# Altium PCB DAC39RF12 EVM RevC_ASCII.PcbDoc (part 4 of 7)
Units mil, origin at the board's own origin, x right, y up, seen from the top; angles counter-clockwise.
Board outline 5071.81 x 2716.54 mil, 16 copper layers (Top Layer, L2 GND1, L3 PWR1, L4 GND2, L5 PWR2, L6 GND3, L7 Ctrl Signal 1, L8 GND4, L9 GND5, L10 Ctrl Signal 2, L11 GND6, L12 PWR3, L13 GND7, L14 PWR4, L15 GND8, Bottom Layer), stack 82.4 mil thick; 596 components, 375 nets, 3310 pads, 1662 vias.
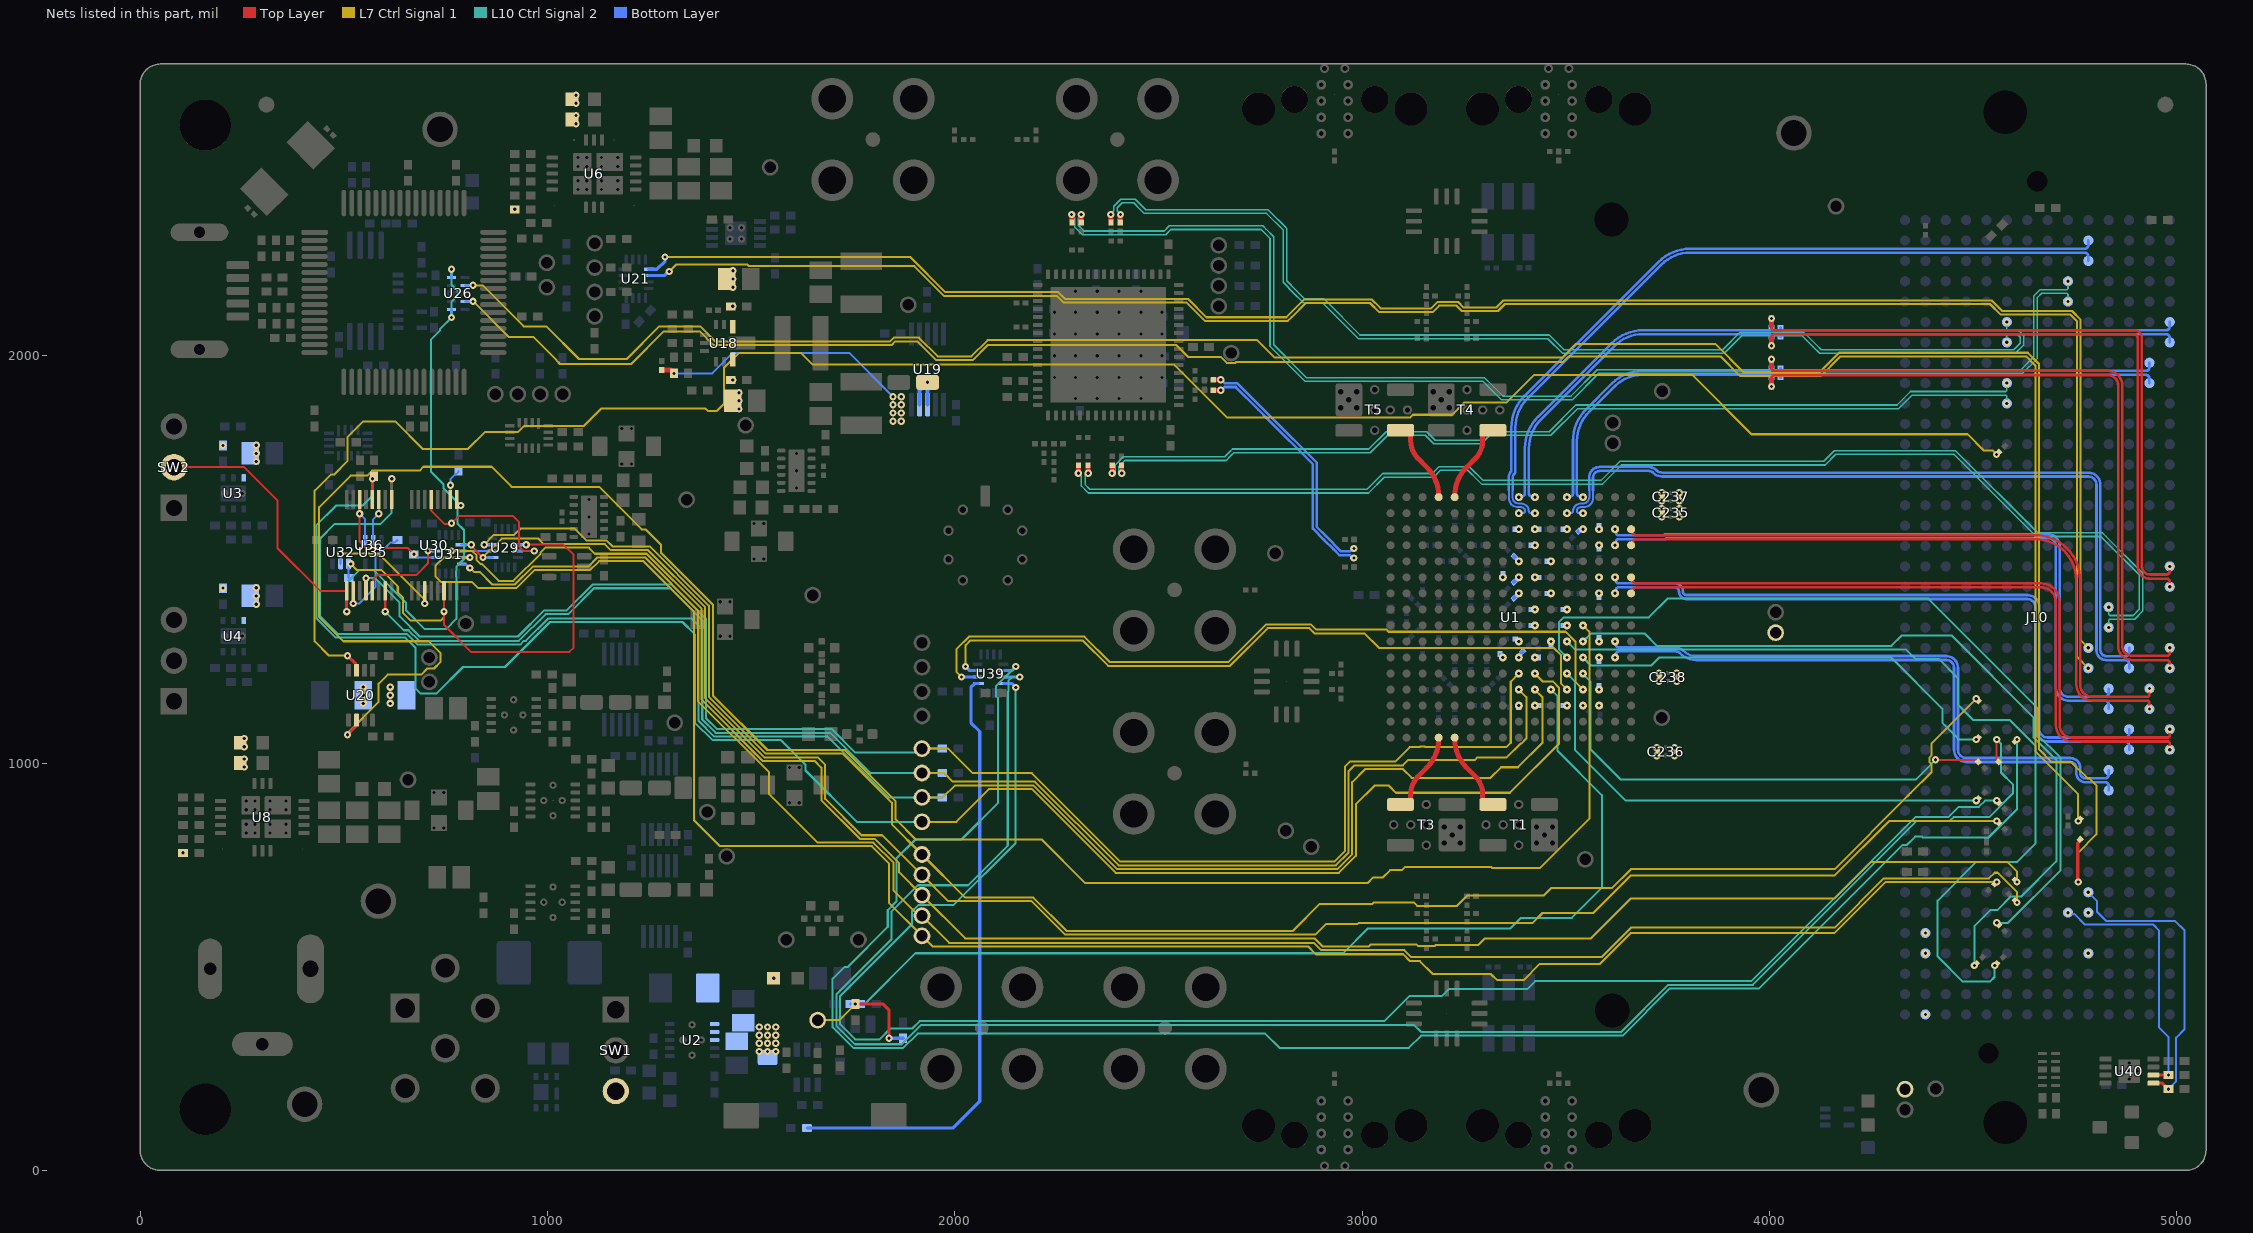
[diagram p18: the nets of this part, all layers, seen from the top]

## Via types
v1: diameter 18, hole 8, Top Layer to Bottom Layer, tented both sides, 1558 vias
v2: diameter 20, hole 10, Top Layer to Bottom Layer, tented both sides, 92 vias
v3: diameter 27, hole 15, Top Layer to Bottom Layer, tented both sides, 12 vias

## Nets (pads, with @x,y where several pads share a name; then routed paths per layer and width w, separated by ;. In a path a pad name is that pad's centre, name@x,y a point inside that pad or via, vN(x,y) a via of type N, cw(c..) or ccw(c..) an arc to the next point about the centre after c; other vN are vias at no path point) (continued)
7SRX_n: J10.B28 U1.G2 | length 1506.9
  Bottom Layer w6.25: v1(3620.99,1298.73) cw(c3615.56,1293.31) 3623.24,1293.31 3623.24,1290.32 ccw(c3629.64,1290.32) 3625.11,1285.8 ccw(c3629.64,1290.33) 3629.64,1283.92 3769.94,1283.92 cw(c3769.94,1258.81) 3787.7,1276.57 ccw(c3820.36,1309.23) 3820.36,1263.04 4433.61,1263.04 cw(c4433.61,1233.82) 4462.84,1233.82 4462.84,1228.44 ; 4462.8,1228.44 4462.8,1033.06 ccw(c4483.23,1033.06) 4483.23,1012.63 4738.89,1012.63 cw(c4738.89,988.86) 4762.66,988.86 4762.66,976.61 ccw(c4776.34,976.61) 4776.34,962.93 4823.97,962.93 ccw(c4823.97,971.77) 4832.81,971.77 J10.B28@4832.81,983.06
7SRX_p: J10.B29 U1.F2 | length 1506.9
  Bottom Layer w6.25: v1(3620.99,1259.36) ccw(c3615.56,1264.79) 3623.24,1264.79 3623.24,1267.77 cw(c3629.64,1267.77) 3625.11,1272.3 cw(c3629.64,1267.77) 3629.64,1274.17 3769.94,1274.17 cw(c3769.94,1258.81) 3780.8,1269.67 ccw(c3820.36,1309.23) 3820.36,1253.29 4433.61,1253.29 cw(c4433.61,1233.82) 4453.09,1233.82 4453.09,1228.44 ; 4453.05,1228.44 4453.05,1033.06 ccw(c4483.23,1033.06) 4483.23,1002.88 4738.89,1002.88 cw(c4738.89,988.86) 4752.91,988.86 4752.91,976.61 ccw(c4776.34,976.61) 4776.34,953.18 4823.97,953.18 cw(c4823.97,944.34) 4832.81,944.34 J10.B29@4832.81,933.06
8SRX_n: R97.2 R98.2 U1.T8 | length 887
  Bottom Layer w6.25: v1(3384.77,1653.06) cw(c3390.19,1647.64) 3390.19,1655.31 3393.18,1655.31 ccw(c3393.18,1661.71) 3397.7,1657.19 ccw(c3393.17,1661.71) 3399.58,1661.71 3399.58,1772.67 cw(c3509.33,1772.67) 3431.72,1850.27 3612.23,2030.79 cw(c3689.84,1953.18) 3689.84,2062.93 3998.37,2062.93 ; 3998.37,2062.93 ccw(c3998.37,2069.56) R97.2@4005,2069.56 cw(c3998.37,2069.56) 3998.37,2062.93
8SRX_p: R99.2 R100.2 U1.T7 | length 871.7
  Bottom Layer w6.25: v1(3424.14,1653.06) ccw(c3418.71,1647.64) 3418.71,1655.31 3415.73,1655.31 cw(c3415.73,1661.71) 3411.2,1657.19 cw(c3415.73,1661.71) 3409.33,1661.71 3409.33,1772.67 cw(c3509.33,1772.67) 3438.62,1843.38 3619.13,2023.89 cw(c3689.84,1953.18) 3689.84,2053.18 3998.37,2053.18 ; 3998.37,2053.18 cw(c3998.37,2046.56) R99.2@4005,2046.56 ccw(c3998.37,2046.56) 3998.37,2053.18
9SRX_n: J10.C2 U1.R8 | length 1882.7
  Bottom Layer w5: 3359.84,1670.39 3360.22,1670.02 3360.22,1650.32 ccw(c3382,1650.32) 3382,1628.54 3388.94,1628.54 cw(c3388.94,1616.08) 3397.74,1624.89 cw(c3392.4,1619.55) 3399.95,1619.55 cw(c3394.09,1619.55) 3394.09,1613.69 v1(3384.77,1613.69)
  Bottom Layer w6.25: 3359.84,1670.39 3359.84,1701.31 cw(c3380.81,1701.31) 3365.98,1716.13 ccw(c3364.75,1717.37) 3366.49,1717.37 3366.49,1824.01 cw(c3476.24,1824.01) 3398.64,1901.62 ; 3398.64,1901.62 3727.81,2230.79 cw(c3805.41,2153.18) 3805.41,2262.93 4773.97,2262.93 ccw(c4773.97,2271.77) 4782.81,2271.77 J10.C2@4782.81,2283.06
9SRX_p: J10.C3 U1.R7 | length 1866.1
  Bottom Layer w5: 3369.59,1670.43 3369.22,1670.06 3369.22,1653.16 ccw(c3384.85,1653.16) 3384.85,1637.54 3389.02,1637.54 cw(c3389.02,1616.29) 3404.04,1631.31 3404.15,1631.21 cw(c3392.54,1619.61) 3408.95,1619.61 3408.95,1619.55 ccw(c3414.81,1619.55) 3414.81,1613.69 v1(3424.14,1613.69)
  Bottom Layer w6.25: 3369.59,1670.43 3369.59,1701.31 cw(c3380.81,1701.31) 3372.88,1709.24 ccw(c3364.75,1717.37) 3376.24,1717.37 3376.24,1824.01 cw(c3476.24,1824.01) 3405.53,1894.72 3734.7,2223.89 cw(c3805.41,2153.18) 3805.41,2253.18 4773.97,2253.18 cw(c4773.97,2244.34) 4782.81,2244.34 J10.C3@4782.81,2233.06
10SRX_n: R92.2 R93.2 U1.T5 | length 728.1
  Bottom Layer w6.25: v1(3502.88,1653.06) cw(c3508.31,1647.64) 3508.31,1655.31 3511.29,1655.31 ccw(c3511.29,1661.71) 3515.81,1657.19 ccw(c3511.29,1661.71) 3517.69,1661.71 3517.69,1790.89 cw(c3627.44,1790.89) 3549.83,1868.49 3614.09,1932.75 cw(c3686.95,1859.9) 3686.95,1962.93 3998.38,1962.93 ccw(c3998.38,1969.56) R92.2@4005,1969.56
10SRX_p: R94.2 R96.2 U1.T4 | length 712.8
  Bottom Layer w6.25: v1(3542.25,1653.06) ccw(c3536.82,1647.64) 3536.82,1655.31 3533.84,1655.31 cw(c3533.84,1661.71) 3529.31,1657.19 cw(c3533.84,1661.71) 3527.44,1661.71 3527.44,1790.89 cw(c3627.44,1790.89) 3556.73,1861.6 3620.99,1925.86 cw(c3686.95,1859.9) 3686.95,1953.18 3998.38,1953.18 cw(c3998.38,1946.56) R94.2@4005,1946.56
11SRX_n: J10.A22 U1.R5 | length 1917.1
  Bottom Layer w5: v1(3502.88,1613.69) 3512.2,1613.69 ccw(c3512.2,1619.55) 3518.06,1619.55 3518.06,1619.61 cw(c3534.47,1619.61) 3522.87,1631.21 3522.97,1631.31 cw(c3537.99,1616.29) 3537.99,1637.54 3542.17,1637.54 ccw(c3542.17,1653.16) 3557.8,1653.16 3557.8,1670.06
  Bottom Layer w6.25: 3557.05,1669.98 3557.05,1700.89 cw(c3583.27,1700.89) 3583.27,1727.12 3703.64,1727.12 cw(c3703.64,1701.74) 3721.59,1719.68 ccw(c3736.7,1734.79) 3736.7,1713.42 4782.21,1713.42 cw(c4782.21,1683.06) 4812.58,1683.06 4812.58,1276.69 ccw(c4826.34,1276.69) 4826.34,1262.93 4873.97,1262.93 ccw(c4873.97,1271.77) 4882.81,1271.77 J10.A22@4882.81,1283.06
11SRX_p: J10.A23 U1.R4 | length 1902.9
  Bottom Layer w5: v1(3542.25,1613.69) 3532.92,1613.69 cw(c3532.92,1619.55) 3527.06,1619.55 cw(c3534.61,1619.55) 3529.27,1624.89 cw(c3538.08,1616.08) 3538.08,1628.54 3545.01,1628.54 ccw(c3545.01,1650.32) 3566.8,1650.32 3566.8,1670.02
  Bottom Layer w6.25: 3566.8,1670.02 3566.8,1700.89 cw(c3583.27,1700.89) 3583.27,1717.37 3703.64,1717.37 cw(c3703.64,1701.74) 3714.69,1712.79 ccw(c3736.7,1734.79) 3736.7,1703.67 4782.21,1703.67 cw(c4782.21,1683.06) 4802.83,1683.06 4802.83,1276.69 ccw(c4826.34,1276.69) 4826.34,1253.18 4873.97,1253.18 cw(c4873.97,1244.34) 4882.81,1244.34 J10.A23@4882.81,1233.06
12SRX_n: J10.Z24 U1.P1 | length 1635.6
  Top Layer w6.25: U1.P1@3660.36,1574.32 ccw(c3675.17,1574.32) 3675.17,1559.51 3698.74,1559.51 4653.05,1559.51 cw(c4653.05,1449.76) 4762.8,1449.76 4762.8,1192.51 ccw(c4792.39,1192.51) 4792.39,1162.93 4927.73,1162.93 ccw(c4927.73,1168.01) 4932.81,1168.01 v1(4932.81,1183.06)
12SRX_p: J10.Z25 U1.N1 | length 1634.9
  Top Layer w6.25: U1.N1@3660.36,1534.95 cw(c3675.17,1534.95) 3675.17,1549.76 4653.05,1549.76 cw(c4653.05,1449.76) 4753.05,1449.76 4753.05,1216.05 ccw(c4815.92,1216.05) 4753.51,1208.47 cw(c4747.3,1207.75) 4753.55,1207.79 4753.55,1192.51 ccw(c4792.39,1192.51) 4792.39,1153.68 4807.66,1153.68 cw(c4807.62,1147.43) 4808.34,1153.64 ccw(c4815.92,1216.05) 4815.92,1153.18 4927.73,1153.18 cw(c4927.73,1148.1) 4932.81,1148.1 v1(4932.81,1133.06)
12V: "U6. "@1065.09,2530 "U8. "@250.73,950.35 C8.2 C9.2 C12.2 C14.2 C19.2 C29.2 C30.2 C33.2 C86.2 C87.2 C88.2 C89.2 D1.1 D3.1 F1.1 R26.2 R28.2 R30.2 R36.2 R47.2 U2.6 U2.7 U2.8 U3.6 U4.6 U18.8 U18.12 | length 113.1
  Top Layer w8: v1(255.73,990.35) C30.2@245.73,1000.35 v1(255.73,1010.35) ; v1(255.73,1040.35) C33.2@245.73,1050.35 v1(255.73,1060.35) ; v1(1070.09,2570) C19.2@1060.09,2580 v1(1070.09,2590) ; v1(1070.09,2620) C29.2@1060.09,2630 v1(1070.09,2640)
  other v1: 1520.24,292.22 1540.24,292.22 1560.24,292.22 1520.24,312.22 1540.24,312.22 1560.24,312.22 1520.24,332.22 1540.24,332.22 1560.24,332.22 1520.24,352.22 1540.24,352.22 1560.24,352.22 1555.26,471.85 105.4,779.98 614.03,1146.72 614.03,1166.72 614.03,1186.72 285.31,1390.42 285.31,1410.42 203.38,1429.79 285.31,1430.42 285.31,1740.42 285.31,1760.42 203.38,1779.79 285.31,1780.42 1470.1,1869.53 1470.1,1889.53 1470.1,1909.53 1455.09,1940.83 1455.09,2121.53 1455.25,2168.58 1455.25,2188.58 1455.25,2208.58 919.76,2359.63
12V_FMC: J10.C35 J10.C37 J10.L36 J10.L37 J10.L40 PP48.1 SW1.3
  other v1: 4382.81,383.06 4382.81,533.06 4782.81,533.06 4382.81,583.06 4782.81,633.06
13SRX_n: J10.B24 U1.P2 | length 1617.3
  Bottom Layer w6.25: v1(3620.99,1574.32) cw(c3615.56,1568.9) 3623.24,1568.9 3623.24,1565.92 ccw(c3629.64,1565.92) 3625.11,1561.39 ccw(c3629.64,1565.92) 3629.64,1559.51 3740.59,1559.51 3743.5,1562.42 4083.63,1562.42 4344.98,1562.43 4663.32,1562.42 cw(c4663.32,1552.68) 4665.77,1562.11 ccw(c4667.29,1568.17) 4667.25,1561.92 4678.9,1561.92 ccw(c4678.87,1568.17) 4680.37,1562.1 cw(c4682.79,1552.68) 4682.79,1562.41 cw(c4682.81,1532.78) 4712.44,1532.78 4712.44,1184.67 ccw(c4734.18,1184.67) 4734.18,1162.93 4823.97,1162.93 ccw(c4823.97,1171.77) 4832.81,1171.77 J10.B24@4832.81,1183.06
13SRX_p: J10.B25 U1.N2 | length 1617
  Bottom Layer w6.25: v1(3620.99,1534.95) ccw(c3615.56,1540.38) 3623.24,1540.38 3623.24,1543.36 cw(c3629.64,1543.36) 3625.11,1547.89 cw(c3629.64,1543.36) 3629.64,1549.76 3744.63,1549.76 3747.54,1552.67 4087.67,1552.67 ; 4087.68,1552.68 4340.94,1552.68 4382.04,1552.67 ccw(c4382.01,1558.92) 4382.19,1552.67 cw(c4382.81,1533.06) 4383.41,1552.67 ccw(c4383.61,1558.92) 4383.57,1552.67 4432.04,1552.67 ccw(c4432.01,1558.92) 4432.19,1552.67 cw(c4432.81,1533.06) 4433.41,1552.67 ccw(c4433.61,1558.92) 4433.57,1552.67 4482.04,1552.67 ccw(c4482.01,1558.92) 4482.19,1552.67 cw(c4482.81,1533.06) 4483.41,1552.67 ccw(c4483.61,1558.92) 4483.57,1552.67 4532.04,1552.67 ccw(c4532.01,1558.92) 4532.19,1552.67 cw(c4532.81,1533.06) 4533.41,1552.67 ccw(c4533.61,1558.92) 4533.57,1552.67 4582.04,1552.67 ccw(c4582.01,1558.92) 4582.19,1552.67 cw(c4582.81,1533.06) 4583.41,1552.67 ccw(c4583.61,1558.92) 4583.57,1552.67 4632.04,1552.67 ccw(c4632.01,1558.92) 4632.19,1552.67 cw(c4632.81,1533.06) 4633.41,1552.67 ccw(c4633.61,1558.92) 4633.57,1552.67 4682.04,1552.67 ccw(c4682.01,1558.92) 4682.19,1552.67 cw(c4682.81,1533.06) 4682.81,1552.68 cw(c4682.81,1533.06) 4683.71,1552.66 ccw(c4683.96,1558.9) 4683.89,1552.66 cw(c4683.8,1533.77) 4702.69,1533.77 4702.69,1187.06 ccw(c4736.56,1187.06) 4703.86,1178.23 cw(c4697.81,1176.63) 4703.91,1178.01 ccw(c4734.18,1184.67) 4727.47,1154.41 cw(c4726.14,1148.31) 4727.74,1154.35 ccw(c4736.56,1187.06) 4736.56,1153.18 4823.97,1153.18 cw(c4823.97,1144.34) 4832.81,1144.34 J10.B25@4832.81,1133.06
14SRX_n: J10.Y26 U1.L1 | length 1694.7
  Top Layer w6.25: U1.L1@3660.36,1456.21 ccw(c3675.17,1456.21) 3675.17,1441.4 3698.74,1441.4 4666.63,1441.4 cw(c4666.63,1395.6) 4712.44,1395.6 4712.44,1093.14 ccw(c4742.64,1093.14) 4742.64,1062.93 4977.73,1062.93 ccw(c4977.73,1068.01) 4982.81,1068.01 v1(4982.81,1083.06)
14SRX_p: J10.Y27 U1.K1 | length 1694
  Top Layer w6.25: U1.K1@3660.36,1416.84 cw(c3675.17,1416.84) 3675.17,1431.65 4666.63,1431.65 cw(c4666.63,1395.6) 4702.69,1395.6 4702.69,1116.68 ccw(c4766.18,1116.68) 4703.14,1109.05 cw(c4696.94,1108.34) 4703.19,1108.37 4703.19,1093.14 ccw(c4742.64,1093.14) 4742.64,1053.68 4757.88,1053.68 cw(c4757.85,1047.43) 4758.56,1053.64 ccw(c4766.18,1116.68) 4766.18,1053.18 4977.73,1053.18 cw(c4977.73,1048.1) 4982.81,1048.1 v1(4982.81,1033.06)
15SRX_n: J10.A26 U1.L2 | length 1633.4
  Bottom Layer w6.25: v1(3620.99,1456.21) cw(c3615.56,1450.79) 3623.24,1450.79 3623.24,1447.81 ccw(c3629.64,1447.81) 3625.11,1443.28 ccw(c3629.64,1447.81) 3629.64,1441.4 3767.54,1441.4 cw(c3767.54,1421.3) 3787.64,1421.3 ccw(c3796.15,1421.3) 3796.15,1412.79 4632.81,1412.79 cw(c4632.81,1383.07) 4662.53,1383.07 4662.53,1083.06 ccw(c4682.65,1083.06) 4682.65,1062.93 4873.97,1062.93 ccw(c4873.97,1071.77) 4882.81,1071.77 J10.A26@4882.81,1083.06
15SRX_p: J10.A27 U1.K2 | length 1633.4
  Bottom Layer w6.25: v1(3620.99,1416.84) ccw(c3615.56,1422.27) 3623.24,1422.27 3623.24,1425.25 cw(c3629.64,1425.25) 3625.11,1429.78 cw(c3629.64,1425.25) 3629.64,1431.65 3767.54,1431.65 cw(c3767.54,1421.3) 3777.89,1421.3 ccw(c3796.15,1421.3) 3796.15,1403.04 4632.81,1403.04 cw(c4632.81,1383.07) 4652.78,1383.07 4652.78,1083.06 ccw(c4682.65,1083.06) 4682.65,1053.18 4873.97,1053.18 cw(c4873.97,1044.34) 4882.81,1044.34 J10.A27@4882.81,1033.06
CCLK_SHIFT: J10.C22 U21.9 | length 4474.9
  L7 Ctrl Signal 1 w5: v1(1288.71,2242.7) 1890.69,2242.7 1976.84,2156.55 2254.21,2156.55 2271.21,2139.55 2572.7,2139.55 2617.58,2094.68 2814.13,2094.68 2858.16,2138.71 3023.06,2138.71 3045.47,2116.3 3169.31,2116.3 3185.36,2132.35 3235.33,2132.35 3248.65,2119.03 3329.78,2119.03 3347.04,2136.29 4545.04,2136.29 4571.33,2110 4742.73,2110 4764,2088.73 4764,1301.87 v1(4782.81,1283.06)
  Bottom Layer w8: U21.9@1248.71,2212.7 1268.71,2212.7 1288.71,2232.7 v1(1288.71,2242.7)
COMM_MUX_CTRL: SW2.1 U26.1 U26.5 U30.1 U36.1 | length 2107.1
  Top Layer w5: SW2.1@82.96,1726.62 255.13,1726.62 337.72,1644.04 337.72,1527.02 441.71,1423.03 U36.1@507.29,1423.03 v1(507.29,1372.03) ; U30.1@777.53,1647.44 777.53,1634.36 779.46,1632.44 v1(786.96,1632.44)
  L10 Ctrl Signal 2 w5: v1(507.29,1372.03) 507.29,1443.27 537.69,1473.67 573.38,1473.67 652.79,1394.26 652.79,1375.17 698.79,1329.17 751.33,1329.17 776.28,1354.13 776.28,1458.34 775.08,1459.54 775.08,1471.55 776.28,1472.75 776.28,1482.34 795.08,1501.14 795.08,1572.33 779.01,1588.4 779.01,1624.49 v1(786.96,1632.44) 744.78,1674.61 744.78,1684.44 714.45,1714.77 714.45,2040.27 736.63,2062.44 736.63,2066 v1(764.51,2093.88) 764.51,2132.75 779.01,2147.25 779.01,2159.26 764.51,2173.76 v1(764.51,2212.62)
  Bottom Layer w8: v1(764.51,2093.88) U26.1@764.51,2113.88 ; U26.5@764.51,2192.62 v1(764.51,2212.62)
DAC_ALARM: U1.H4 U20.6 | length 5302.3
  Top Layer w8: v1(509.15,1069.73) 529.49,1090.07 529.49,1103.93 U20.6@531.4,1105.84
  L7 Ctrl Signal 1 w5: v1(509.15,1069.73) 509.15,1073.83 585.58,1150.25 585.58,1195.34 607.57,1217.34 689.97,1217.34 704.99,1232.36 721.36,1232.36 737.18,1248.18 737.18,1270.54 708.46,1299.27 499.09,1299.27 439.71,1358.65 439.71,1628.63 516.94,1705.86 557.21,1705.86 569.65,1718.31 686.02,1718.31 695.34,1727.63 862.8,1727.63 912,1678.44 1126.87,1678.44 1231.2,1574.11 1240.77,1574.11 1278.73,1536.15 1278.73,1516.75 1406.46,1389.01 1406.46,1165.85 1540.1,1032.21 1729.37,1032.21 1854.7,906.87 1854.7,862.13 1904.23,812.59 2213.44,812.59 2320.57,705.47 3013.1,705.47 3027.23,719.59 3051.27,719.59 3069.03,737.35 3097.59,737.35 3105.56,745.33 3316.86,745.33 3319.5,742.68 3431.45,742.68 3432.06,742.07 3436.2,742.07 3557.79,863.66 3557.79,1322.56 v1(3542.25,1338.1)
DAC_ALARM_FMC: R156.1 U20.3 | length 5116.9
  Top Layer w8: v1(509.15,1263.99) 529.49,1243.64 529.49,1229.79 U20.3@531.4,1227.88
  L7 Ctrl Signal 1 w5: v1(509.15,1263.99) 463.68,1263.99 428.5,1299.17 428.5,1668.73 468.07,1708.3 475.89,1708.3 508.85,1741.26 508.85,1800.12 547.74,1839.01 626.07,1839.01 693.77,1771.31 804.77,1771.31 846.18,1812.71 927.55,1812.71 942.8,1827.97 1089.66,1827.97 1132.33,1870.63 1387.67,1870.63 1393.62,1864.68 1416.29,1864.68 1433.44,1881.84 1433.44,1970.5 1470.38,2007.44 1622.13,2007.44 1650.45,1979.12 2537.56,1979.12 2667.69,1848.99 3118.59,1848.99 3124.91,1855.31 3220.94,1855.31 3235.54,1869.91 3235.54,1870.38 3250.15,1884.99 3354.06,1884.99 3422.25,1953.18 3810.11,1953.18 3955.85,1807.45 4486.5,1807.45 4526.39,1767.56 4547.7,1767.56 v1(4557.5,1757.75)
DAC_C\S\: PP39.1 R186.2 U1.E7 U36.12 | length 4642.7
  Top Layer w5: U36.12@570.28,1647.44 v1(570.28,1698.44) 574.28,1702.44 R186.2@574.28,1704.44
  L7 Ctrl Signal 1 w5: PP39.1@1919.48,855.8 2004.05,855.8 2084.93,936.68 2189.28,936.68 2395.07,730.89 2942.87,730.89 2984.6,772.62 2984.6,898.83 3030.83,945.06 3065.14,945.06 3082.89,927.31 3362.7,927.31 3483.28,1047.89 3483.28,1185.52 3468.74,1200.06 3444.07,1200.06 v1(3424.14,1219.99)
  L10 Ctrl Signal 2 w5: v1(570.28,1698.44) 570.28,1655.96 546.76,1632.44 481.28,1632.44 432.66,1583.82 432.66,1356.34 480.74,1308.27 651.27,1308.27 675.61,1283.93 675.61,1183.6 687.84,1171.37 727.86,1171.37 792.58,1236.1 895.73,1236.1 1006.26,1346.63 1331.46,1346.63 1361.96,1316.12 1361.96,1099.69 1405.37,1056.29 1573.28,1056.29 1633.58,995.99 1633.58,981.99 1759.77,855.8 PP39.1@1919.48,855.8
DAC_R\E\S\E\T\: R194.2 U39.1 | length 1499.8
  Bottom Layer w8: R194.2@1637.03,104.19 1995.39,104.19 2061.37,170.17 2061.37,1077.77 2039.57,1099.57 2039.57,1185.99 2048.64,1195.06 2048.64,1195.74 2048.7,1195.8 U39.1@2058.42,1195.8
DAC_R\E\S\E\T\_DUT: C170.2 PP40.1 R143.1 R145.1 R147.1 U1.D6 | length 2815.2
  Top Layer w8: v1(1755.73,408.61) 1824.22,408.61 1838.33,394.5 v1(1838.33,324.38)
  L7 Ctrl Signal 1 w5: PP40.1@1663.3,369.24 1716.36,369.24 v1(1755.73,408.61)
  L10 Ctrl Signal 2 w5: v1(1755.73,408.61) 1778.39,408.61 1903.1,533.32 2953.28,533.32 3014.11,594.16 3363.94,594.16 3390.02,620.23 3514.77,620.23 3588.42,693.88 3588.42,921.37 3480.01,1029.78 3480.01,1164.12 v1(3463.51,1180.62)
  Bottom Layer w8: R145.1@1743.92,408.61 R147.1@1767.54,408.61 ; v1(1838.33,324.38) R143.1@1873.33,324.38
DAC_R\E\S\E\T\_FMC: R165.1 U39.12 | length 4188.1
  Top Layer w5: v1@4557.5,908.36 v1(4557.81,908.06)
  L10 Ctrl Signal 2 w5: v1(2149.44,1185.8) 2149.44,804.08 1996.66,651.3 1910.34,651.3 1894.98,635.95 1894.98,604.95 1718.33,428.29 1718.33,359.02 1755.36,322 1815.44,322 1842.06,348.61 1895.59,348.61 1913.63,366.65 3054.46,366.65 3115.97,428.16 3195.56,428.16 3213.51,446.12 3406.16,446.12 3424.96,464.92 3955.6,464.92 4358.23,867.56 4439.23,867.56 4464.23,892.56 4514.23,892.56 4529.73,908.06 v1(4557.81,908.06)
  Bottom Layer w8: U39.12@2119.44,1195.8 2139.44,1195.8 v1(2149.44,1185.8)
DAC_SCLK: PP36.1 R188.1 U1.E8 U36.4 | length 3877.5
  Top Layer w8: U36.4@554.53,1423.03 v1(554.53,1454.03)
  L7 Ctrl Signal 1 w5: PP36.1@1919.48,1035.8 1983.79,1035.8 2044.2,975.39 2189.17,975.39 2406.38,758.18 2931.57,758.18 2957.6,784.22 2957.6,991.62 2969.67,1003.68 3081.45,1003.68 3116.88,1039.12 3140.87,1039.12 3142.15,1040.4 3154.16,1040.4 3155.45,1039.12 3353.93,1039.12 3364.88,1050.07 3364.88,1200.11 v1(3384.77,1219.99)
  L10 Ctrl Signal 2 w5: v1(554.53,1454.03) 577.45,1454.03 637.2,1394.27 637.2,1360.64 686.94,1310.9 927.63,1310.9 991.76,1375.03 1047.16,1375.03 1110.51,1438.38 1292.47,1438.38 ; 1292.48,1438.37 1305.2,1438.37 1389.02,1354.55 1389.02,1341.82 1389.02,1110.93 1416.59,1083.37 1698.5,1083.37 1756.07,1025.8 1899.74,1025.8 1909.74,1035.8 PP36.1@1919.48,1035.8
  Bottom Layer w5: PP36.1@1919.48,1035.8 R188.1@1969.48,1035.8
DAC_SDI: PP37.1 R189.1 U1.D8 U36.7 | length 3784.5
  Top Layer w5: v1(601.78,1372.03) U36.7@601.78,1423.03
  L7 Ctrl Signal 1 w5: PP37.1@1919.48,975.8 1974.07,975.8 1995.19,954.68 2196.73,954.68 2402.53,748.89 2935.42,748.89 2966.6,780.07 2966.6,980.01 2981.27,994.68 3099.74,994.68 3113.26,1008.2 3277.22,1008.2 3283.11,1014.1 3354.86,1014.1 3388.77,1048.01 3390.77,1048.01 3403.35,1060.58 3403.35,1162.04 v1(3384.77,1180.62)
  L10 Ctrl Signal 2 w5: v1(601.78,1372.03) 647.54,1326.27 658.73,1326.27 684.91,1300.08 929.55,1300.08 995.49,1366.03 1050.89,1366.03 1114.23,1429.37 1301.48,1429.37 1380.02,1350.82 1380.02,1107.21 1412.86,1074.37 1693.92,1074.37 1792.49,975.8 PP37.1@1919.48,975.8
  Bottom Layer w5: PP37.1@1919.48,975.8 R189.1@1969.48,975.8
DAC_SDO: PP38.1 R190.1 U1.D7 U36.9 | length 4439.4
  Top Layer w5: U36.9@617.53,1647.44 v1(617.53,1698.44)
  L7 Ctrl Signal 1 w5: PP38.1@1919.48,915.8 1970.75,915.8 2000.62,945.68 2193.01,945.68 2398.8,739.89 2939.14,739.89 2975.6,776.34 2975.6,953.33 3007.96,985.68 3100.06,985.68 3121.77,963.97 3315.24,963.97 3341.24,989.97 3382.17,989.97 3442.75,1050.56 3442.75,1162.01 v1(3424.14,1180.62)
  L10 Ctrl Signal 2 w5: v1(617.53,1698.44) 617.53,1614.54 590.4,1587.42 478.09,1587.42 441.66,1550.99 441.66,1360.07 484.47,1317.27 655,1317.27 681.18,1291.08 933.27,1291.08 942.27,1300.08 946.99,1300.08 1002.54,1355.63 1352.68,1355.63 1370.96,1337.35 1370.96,1103.42 1409.1,1065.29 1687.93,1065.29 1837.42,915.8 PP38.1@1919.48,915.8
  Bottom Layer w5: PP38.1@1919.48,915.8 R190.1@1969.48,915.8
DAC_SYSREF_LMK_N: C81.1 R109.2 | length 614.8
  Top Layer w12.1: C81.1@2634.75,1941.17 v1(2652.7,1941.17)
  Bottom Layer w6.25: v1(2652.7,1941.17) 2654.27,1941.17 2662.24,1933.2 2693.25,1933.2 2777.37,1849.08 2888.61,1737.84 2888.61,1579.82 2910.89,1557.54 2948.29,1520.14 2970.2,1520.14 2976.82,1526.77 v1(2979.81,1526.77)
DAC_SYSREF_LMK_P: C77.1 R107.2 | length 614.8
  Top Layer w12.1: C77.1@2634.75,1915.48 v1(2652.7,1915.48)
  Bottom Layer w6.25: v1(2652.7,1915.48) 2654.27,1915.48 2662.24,1923.45 2689.22,1923.45 2745.1,1867.56 2767.62,1845.04 2878.86,1733.8 2878.86,1575.78 2906.85,1547.79 2929.37,1525.27 2944.25,1510.39 2970.2,1510.39 2976.82,1503.77 v1(2979.81,1503.77)
DAC_TXEN0: U1.D5 U39.3 | length 1738.2
  L7 Ctrl Signal 1 w5: v1(2026.45,1237.3) 2026.45,1289.55 2038.02,1301.12 2314.13,1301.12 2376.41,1238.84 2675.64,1238.84 2768.11,1331.31 2870.61,1331.31 2883.13,1318.79 3005.71,1318.79 3041.51,1282.98 3469.81,1282.98 3488.38,1264.41 3488.38,1195.12 v1(3502.88,1180.62) v1@3505.36,1183.11
  Bottom Layer w8: v1(2026.45,1237.3) 2036.45,1227.3 U39.3@2056.45,1227.3
DAC_TXEN0_FMC: R161.1 U39.10 | length 4554
  L10 Ctrl Signal 2 w5: v1(2149.44,1237.3) 2101,1188.86 2101,1164.44 2106.44,1159 2106.44,902.59 2016.45,812.59 1903.5,812.59 1856.95,766.04 1856.95,660.65 1835.41,639.1 1835.41,598.25 1736.58,499.41 1729.01,499.41 1700.33,470.74 1700.33,351.57 1751.01,300.88 1873.32,300.88 1908.63,336.19 2761.93,336.19 2797.18,300.94 3114.61,300.94 3144.65,330.99 3639.51,330.99 3755.45,446.92 3974.76,446.92 4326.39,798.56 4336.43,798.56 4357.66,819.78 4374.16,819.78 4376.39,817.56 4537.82,817.56 4607.81,887.55 v1(4607.81,1058.06)
  Bottom Layer w8: U39.10@2119.44,1227.3 2139.44,1227.3 v1(2149.44,1237.3)
DAC_TXEN1: U1.D4 U39.2 | length 1853.1
  L7 Ctrl Signal 1 w5: v1(2016.45,1211.55) 2004.58,1223.42 2004.58,1280.41 2034.9,1310.73 2318.11,1310.73 2381.01,1247.84 2671.05,1247.84 2764.13,1340.92 2873.72,1340.92 2886.24,1328.4 3059,1328.4 3064.8,1322.6 3499.51,1322.6 3523.38,1298.73 3523.38,1199.49 v1(3542.25,1180.62)
  Bottom Layer w8: v1(2016.45,1211.55) U39.2@2056.45,1211.55
DAC_TXEN1_FMC: R163.1 U39.11 | length 4548.9
  Top Layer w5: v1(4557.81,1058.06) 4557.81,1013.24 4562.52,1008.54 R163.1@4562.52,1003.35
  L10 Ctrl Signal 2 w5: v1(2159.44,1211.55) 2140.49,1211.55 2131.5,1202.56 2131.5,1176.06 2130,1174.56 2130,797.37 2032.93,700.3 1909.34,700.3 1844.41,635.38 1844.41,567.1 1709.33,432.02 1709.33,355.29 1754.74,309.88 1869.59,309.88 1917.36,357.65 3126.99,357.65 3144.65,339.99 3635.78,339.99 3751.72,455.92 3959.32,455.92 4361.96,858.56 4442.96,858.56 4451.96,867.56 4539.23,867.56 4598.31,926.63 4598.31,947.05 4568.31,977.05 4568.31,1047.56 v1(4557.81,1058.06)
  Bottom Layer w8: U39.11@2119.44,1211.55 v1(2159.44,1211.55)
DACOUTA_n: T3.1 U1.A13 | length 204.9
  Top Layer w12.3: T3.1@3094.22,898.59 3109.87,898.59 3119.27,907.99 3119.27,923.53 cw(c3181.84,923.53) 3137.6,967.77 3158.63,988.8 ccw(c3087.92,1059.51) 3187.92,1059.51 U1.A13@3187.92,1062.51
DACOUTA_p: T1.1 U1.A12 | length 233.9
  Top Layer w12.3: U1.A12@3227.29,1062.51 3227.29,1059.51 ccw(c3327.29,1059.51) 3256.58,988.8 3277.61,967.77 cw(c3233.37,923.53) 3295.93,923.53 T1.1@3295.93,907.99 ; T1.1@3295.93,907.99 T1.1@3305.33,898.59 ; T1.1@3295.93,907.99 T1.1@3305.33,898.59 ; T1.1@3305.33,898.59 T1.1@3320.99,898.59 T1.1@3305.33,898.59
DACOUTB_n: T5.1 U1.T13 | length 233.9
  Top Layer w12.3: U1.T13@3187.92,1653.06 3187.92,1656.06 ccw(c3087.92,1656.06) 3158.63,1726.77 3137.6,1747.8 cw(c3181.84,1792.04) 3119.27,1792.04 T5.1@3119.27,1807.59 ; T5.1@3109.87,1816.99 T5.1@3119.27,1807.59 ; T5.1@3109.87,1816.99 T5.1@3119.27,1807.59 ; T5.1@3109.87,1816.99 T5.1@3094.22,1816.99 T5.1@3109.87,1816.99
DACOUTB_p: T4.1 U1.T12 | length 204.9
  Top Layer w12.3: U1.T12@3227.29,1653.06 3227.29,1656.06 cw(c3327.29,1656.06) 3256.58,1726.77 3277.61,1747.8 ccw(c3233.37,1792.04) 3295.93,1792.04 3295.93,1807.59 3305.33,1816.99 T4.1@3320.99,1816.99
DIN_SHIFT: J10.C23 U21.10 | length 4504.5
  L7 Ctrl Signal 1 w5: v1(1298.71,2206.95) 1315.84,2224.08 1490.72,2224.08 1494.8,2220 1900.66,2220 1974.08,2146.58 2251.45,2146.58 2267.48,2130.55 2568.98,2130.55 2613.85,2085.68 2817.85,2085.68 2826.85,2094.68 2861.88,2129.71 3019.33,2129.71 3041.75,2107.3 3173.04,2107.3 3189.08,2123.35 3231.6,2123.35 3244.92,2110.03 3333.51,2110.03 3350.77,2127.29 4541.31,2127.29 4567.6,2101 4739,2101 4755,2085 4755,1260.87 v1(4782.81,1233.06)
  L7 Ctrl Signal 1 w8: v1(1298.71,2206.95) v1@1300,2205.66
  Bottom Layer w8: U21.10@1248.71,2196.95 1286.74,2196.95 1296.74,2206.95 v1(1298.71,2206.95)
DP14_M2C_N: J10.Y19 R100.1 | length 1602.2
  Top Layer w6.3: 4005,2044.51 cw(c4013.4,2044.51) 4013.4,2052.91 4895,2052.91 cw(c4895,2043.88) 4904.03,2043.88 4904.03,1483.06 ccw(c4934.18,1483.06) 4934.18,1452.91 4974.88,1452.91 cw(c4974.88,1444.97) 4982.81,1444.97 v1(4982.81,1433.06)
  Top Layer w12.1: v1(4005,2024.51) 4005,2044.51
DP14_M2C_P: J10.Y18 R98.1 | length 1602.2
  Top Layer w6.3: 4005,2071.6 ccw(c4013.4,2071.6) 4013.4,2063.21 4895,2063.21 cw(c4895,2043.88) 4914.33,2043.88 4914.33,1483.06 ccw(c4934.18,1483.06) 4934.18,1463.21 4974.88,1463.21 ccw(c4974.88,1471.14) 4982.81,1471.14 v1(4982.81,1483.06)
  Top Layer w12.1: 4005,2071.6 v1(4005,2091.6)
DP15_M2C_N: J10.Y23 R96.1 | length 1693.1
  Top Layer w6.3: 4005,1944.51 cw(c4013.12,1944.51) 4013.12,1952.63 4830.09,1952.63 cw(c4830.09,1926.72) 4855.99,1926.72 4855.99,1287.38 ccw(c4890.47,1287.38) 4890.47,1252.91 4975.74,1252.91 cw(c4975.74,1245.83) 4982.81,1245.83 v1(4982.81,1233.06)
  Top Layer w12.1: v1(4005,1924.51) 4005,1944.51
DP15_M2C_P: J10.Y22 R93.1 | length 1694.1
  Top Layer w6.3: 4005,1971.6 4005,1968.01 4007.54,1965.47 4010.08,1962.93 4830.09,1962.93 cw(c4830.09,1926.72) 4866.29,1926.72 4866.29,1287.38 ccw(c4890.47,1287.38) 4890.47,1263.21 4975.74,1263.21 ccw(c4975.74,1270.28) 4982.81,1270.28 v1(4982.81,1283.06)
  Top Layer w12.1: 4005,1971.6 v1(4005,1991.6)
DP20_M2C_N: J10.Z9 R94.1 | length 925.9
  Bottom Layer w6.25: R94.1@4027.05,1946.56 cw(c4033.67,1946.56) 4033.67,1953.18 4923.97,1953.18 cw(c4923.97,1944.34) 4932.81,1944.34 J10.Z9@4932.81,1933.06
DP20_M2C_P: J10.Z8 R92.1 | length 925.9
  Bottom Layer w6.25: R92.1@4027.05,1969.56 ccw(c4033.67,1969.56) 4033.67,1962.93 4923.97,1962.93 ccw(c4923.97,1971.77) 4932.81,1971.77 J10.Z8@4932.81,1983.06
DP21_M2C_N: J10.Y7 R99.1 | length 975.9
  Bottom Layer w6.25: R99.1@4027.05,2046.56 cw(c4033.67,2046.56) 4033.67,2053.18 4973.97,2053.18 cw(c4973.97,2044.34) 4982.81,2044.34 J10.Y7@4982.81,2033.06
DP21_M2C_P: J10.Y6 R97.1 | length 975.9
  Bottom Layer w6.25: R97.1@4027.05,2069.56 ccw(c4033.67,2069.56) 4033.67,2062.93 4973.97,2062.93 ccw(c4973.97,2071.77) 4982.81,2071.77 J10.Y6@4982.81,2083.06
DVDD: C43.2 C173.2 C174.2 C175.2 C176.2 C177.2 C178.2 C179.2 C180.2 C181.2 C182.2 C183.2 C184.2 C185.2 C186.2 C187.2 C188.2 C189.2 C190.2 C191.2 C192.2 C193.2 C194.2 C195.2 C210.2 C211.2 C212.2 C213.2 C214.2 C215.2 C216.2 C217.2 C218.2 C235.1 C235.3 C236.1 C236.3 C237.1 C237.3 C238.1 C238.3 R84.1 R87.2 U1.C3 U1.C4 U1.C5 U1.C7 U1.C8 U1.D3 U1.F3 U1.F7 U1.F8 U1.F9 U1.G3 U1.G6 U1.G8 U1.H5 U1.H7 U1.J5 U1.J7 U1.K3 U1.K6 U1.K8 U1.L3 U1.L7 U1.L8 U1.L9 U1.M6 U1.M8 U1.N3 U1.N7 U1.P3 U1.P4 U1.P5 U1.P7 U1.P8 U19.8 U19.9 | length 1221.6
  Top Layer w10: v1(3723.63,1018.04) 3724.72,1019.14 3724.72,1027.14 C236.3@3725.63,1028.04 3724.72,1028.95 3724.72,1036.95 v1(3723.63,1038.04) ; v1(3728.93,1201.1) 3730.02,1202.19 3730.02,1210.19 C238.3@3730.93,1211.1 3730.02,1212 3730.02,1220 v1(3728.93,1221.1) ; v1(3735.49,1604.22) 3736.59,1605.31 3736.59,1613.31 C235.3@3737.49,1614.22 3736.59,1615.12 3736.59,1623.12 v1(3735.49,1624.22) ; v1(3735.49,1643.9) 3736.59,1645 3736.59,1653 C237.3@3737.49,1653.9 3736.59,1654.81 3736.59,1662.81 v1(3735.49,1663.9) ; v1(3767,1018.04) 3765.9,1019.14 3765.9,1027.14 C236.1@3765,1028.04 3765.9,1028.95 3765.9,1036.95 v1(3767,1038.04) ; v1(3772.3,1201.1) 3771.2,1202.19 3771.2,1210.19 C238.1@3770.3,1211.1 3771.2,1212 3771.2,1220 v1(3772.3,1221.1) ; v1(3778.86,1604.22) 3777.77,1605.31 3777.77,1613.31 C235.1@3776.86,1614.22 3777.77,1615.12 3777.77,1623.12 v1(3778.86,1624.22) ; v1(3778.86,1643.9) 3777.77,1645 3777.77,1653 C237.1@3776.86,1653.9 3777.77,1654.81 3777.77,1662.81 v1(3778.86,1663.9)
  Top Layer w12: C43.2@1280.62,1965.47 1301.96,1965.47 1304.81,1962.62 1306.78,1962.62 1310.62,1958.78 v1(1310.62,1956.81)
  Bottom Layer w5: v1(1310.62,1956.81) 1404.67,1956.81 1455.3,2007.44 1740.44,2007.44 v1(1848.25,1899.63) ; C183.2@3338.4,1268.02 3345.4,1261.02 v1(3345.4,1259.36) ; v1(3345.4,1456.21) C179.2@3345.4,1464.87 ; C184.2@3376.1,1298.73 v1(3384.77,1298.73) ; C218.2@3376.11,1574.32 v1(3384.77,1574.32) ; C211.2@3415.48,1338.1 v1(3424.14,1338.1) ; C177.2@3415.48,1377.47 v1(3424.14,1377.47) ; C215.2@3415.48,1534.95 v1(3424.14,1534.95) ; v1(3424.14,1141.25) C193.2@3432.8,1141.25 ; v1(3424.14,1259.36) C175.2@3430.74,1259.36 ; v1(3424.14,1456.21) C213.2@3432.8,1456.21 ; v1(3424.14,1574.32) C182.2@3432.8,1574.32 ; C186.2@3454.85,1416.84 v1(3463.51,1416.84) ; C178.2@3454.85,1495.58 v1(3463.51,1495.58) ; C176.2@3463.51,1290.07 v1(3463.51,1298.73) ; C191.2@3494.22,1141.25 v1(3502.88,1141.25) ; C212.2@3494.22,1338.1 v1(3502.88,1338.1) ; C185.2@3494.22,1377.47 v1(3502.88,1377.47) ; C217.2@3494.22,1574.32 v1(3502.88,1574.32) ; v1(3581.62,1141.25) C194.2@3583.62,1141.25 ; v1(3581.62,1180.62) C195.2@3581.62,1189.28 ; C190.2@3581.62,1250.7 v1(3581.62,1259.36) ; v1(3581.62,1298.73) C189.2@3581.62,1307.39 ; C192.2@3581.62,1408.18 v1(3581.62,1416.84) ; C180.2@3581.62,1526.29 v1(3581.62,1534.95) ; v1(3581.62,1574.32) C216.2@3581.62,1582.99
  Bottom Layer w10: U19.9@1913.39,1880.18 1913.39,1915.11 v1(1933.07,1934.79) U19.8@1933.07,1880.18 ; C187.2@3372.88,1404.95 v1(3384.77,1416.84) ; C214.2@3372.88,1444.32 v1(3384.77,1456.21) ; C188.2@3372.88,1507.47 v1(3384.77,1495.58) ; v1(3384.77,1259.36) 3386.3,1260.89 3386.3,1265.06 3393.77,1272.53 C210.2@3393.77,1274.36 ; C181.2@3531.25,1569.32 3533.09,1569.32 3536.55,1572.79 3540.72,1572.79 v1(3542.25,1574.32)
  other v1: 3384.77,1141.25 3542.25,1141.25 3581.62,1456.21 1848.25,1839.63 1868.25,1839.63 1848.25,1859.63 1868.25,1859.63 1848.25,1879.63 1868.25,1879.63 1868.25,1899.63
fanPwr: PP1.1 R25.1 R26.1
  other v1: 547.74,1146.72 547.74,1166.72 547.74,1186.72
FMC_C\S\_DAC: PP28.1 R168.1 U31.3 | length 4900.7
  Top Layer w5: R168.1@4553.12,703.35 v1(4557.83,708.06)
  L7 Ctrl Signal 1 w5: v1(809.58,1504.92) 745.27,1504.92 724.84,1484.49 724.84,1459.12 739.64,1444.33 815.07,1444.33 829.87,1429.53 923.81,1429.53 967.95,1473.67 1104.22,1473.67 1126.64,1496.09 1235.74,1496.09 1360.3,1371.53 1360.3,859.29 1423.54,796.05 1796.27,796.05 1838.33,753.99 1838.33,656.95 PP28.1@1919.48,575.8 1945.29,550 2867.19,550 2886.36,530.83 3100.67,530.83 3117.47,514.04 3141.58,514.04 3173.15,482.47 3316.2,482.47 3331.23,467.44 3396.39,467.44 3436.26,507.31 3583.87,507.31 3660,583.44 4160,583.44 4284.62,708.06 v1(4557.83,708.06)
  Bottom Layer w5: U31.3@789.58,1504.92 v1(809.58,1504.92)
FMC_C\S\_LMK: PP26.1 R158.1 U29.3 | length 4566.1
  Top Layer w8: v1(4507.81,1158.06) R158.1@4512.52,1153.35
  L7 Ctrl Signal 1 w5: v1(844.58,1536.41) 868.45,1560.28 918.24,1560.28 933.74,1575.78 1066.64,1575.78 1095.54,1546.87 1144.82,1546.87 1159.61,1532.09 1250.66,1532.09 1387.3,1395.45 1396.3,1386.45 1396.3,1163.28 1536.37,1023.21 1725.64,1023.21 1845.7,903.14 1845.7,849.58 PP26.1@1919.48,775.8 2025.25,670.03 2192.57,670.03 2274.6,588 2830,588 2896.44,654.44 3025.4,654.44 3029.06,658.11 3126.7,658.11 3135.23,649.58 3232.86,649.58 3258.73,675.44 3446.46,675.44 3464.9,693.88 3613.88,693.88 3660,740 4160,740 4338.56,918.56 4338.82,918.56 4347.31,927.05 4347.31,927.31 4398.31,978.31 4398.31,997.05 4393.31,1002.05 4393.31,1014.06 4398.31,1019.06 4398.31,1048.55 v1(4507.81,1158.06)
  Bottom Layer w5: v1(844.58,1536.41) U29.3@864.58,1536.41
FMC_C\S\_LMK_3p3: R135.2 U29.10 U30.14 U32.1 | length 1177.2
  Top Layer w5: U30.14@746.03,1423.03 v1(746.03,1372.03) 746.03,1339.45 812.05,1273.43 1053.89,1273.43 1064.04,1283.58 1064.04,1511.47 1039.1,1536.41 v1(947.57,1536.41)
  L7 Ctrl Signal 1 w5: v1(516.94,1489.17) 532.44,1473.67 592.83,1473.67 632.5,1433.99 632.5,1419.15 644.86,1406.79 644.86,1369.33 664.11,1350.08 737.68,1350.08 746.03,1358.43 v1(746.03,1372.03)
  Bottom Layer w5: R135.2@511.94,1454.17 U32.1@511.94,1489.17 ; U29.10@927.57,1536.41 v1(947.57,1536.41)
FMC_CS_DAC_1p8: R140.2 U31.10 U35.1 U36.14 | length 410
  Top Layer w5: v1(538.79,1612.44) 538.79,1544.07 554.57,1528.29 656.69,1528.29 v1(672.19,1512.79)
  Top Layer w8: v1(538.79,1612.44) U36.14@538.79,1647.44 v1@538.79,1616.44
  Bottom Layer w5: v1(538.79,1612.44) 552.57,1598.66 U35.1@552.57,1547.44 ; R140.2@671.31,1512.79 v1(672.19,1512.79) 673.28,1512.79 681.15,1504.92 U31.10@726.59,1504.92
FMC_F\R\C\S\: R172.1 U1.G4 | length 1961.1
  Top Layer w5: v1@4502.8,503.04 v1(4503.11,503.35)
  L10 Ctrl Signal 2 w5: v1(3542.25,1298.73) 3562.02,1318.5 3693.19,1318.5 3723.56,1288.13 4299.37,1288.13 4324.69,1313.46 4447.05,1313.46 4648.81,1111.7 4648.81,1062.96 4700.96,1010.81 4701.17,1010.81 4704.1,1007.88 4704.1,758.84 4617.82,672.56 4592.82,672.56 4559.95,639.69 4542.79,639.69 4503.11,600.01 v1(4503.11,503.35)
FMC_FRCLK: R159.1 U1.F4 | length 1085.6
  Top Layer w5: v1@4507.5,1057.75 v1(4507.81,1058.06)
  L10 Ctrl Signal 2 w5: v1(3542.25,1259.36) 3561.85,1239.76 3709.88,1239.76 3729.48,1259.36 4299.01,1259.36 4424.59,1133.78 4424.59,1099.63 4466.16,1058.06 v1(4507.81,1058.06)
FMC_FRDI0: R160.1 U1.E4 | length 1198.5
  Top Layer w5: v1(4407.81,1008.06) 4502.62,1008.06 4507.33,1003.35 R160.1@4512.52,1003.35
  L10 Ctrl Signal 2 w5: v1(3542.25,1219.99) 3542.25,1218.68 3560.26,1200.67 3560.26,1153.42 3560.09,1153.25 3560.09,1034.74 3635,959.83 4144.63,959.83 4145,959.46 4359.22,959.46 v1(4407.81,1008.06)
FMC_FRDI1: R162.1 U1.E5 | length 1233
  Top Layer w5: v1@4507.5,907.75 v1(4507.81,908.06)
  L10 Ctrl Signal 2 w5: v1(3502.88,1219.99) 3522.18,1200.69 3522.18,1032.66 3646.79,908.06 v1(4507.81,908.06)
FMC_FRDI2: R176.1 U1.F5 | length 2037.7
  Top Layer w5: v1@4557.5,608.36 v1(4557.81,608.06)
  L10 Ctrl Signal 2 w5: v1(3502.88,1259.36) 3483.11,1279.13 3483.11,1346.22 3494.76,1357.87 3703.82,1357.87 3749.74,1403.79 4389.8,1403.79 4657.81,1135.77 4657.81,1069.83 4714.82,1012.81 4714.82,737.35 4585.53,608.06 v1(4557.81,608.06)
FMC_FRDI3: R177.1 U1.G5 | length 2168.8
  Top Layer w5: v1@4552.8,503.04 v1(4553.11,503.35)
  L10 Ctrl Signal 2 w5: v1(3502.88,1298.73) 3522.48,1279.13 4334.58,1279.13 4357.66,1256.06 4415.54,1256.06 4462.58,1209.02 4462.58,1143.94 4500.66,1105.86 4590.24,1105.86 4652.74,1043.36 4652.74,802.35 4607.92,757.53 4508.05,757.53 4412.78,662.25 4412.78,525.37 4474.69,463.46 4540.93,463.46 4552.41,474.94 4552.41,502.66 v1(4553.11,503.35)
FMC_I2C_SCL: R152.1 U26.9 | length 5247
  Top Layer w8: v1(4757.81,858.06) R152.1@4762.52,862.76
  L7 Ctrl Signal 1 w5: v1(817.38,2133.57) 904.26,2046.69 964.98,2046.69 1021.74,1989.93 1021.74,1989.04 1030.82,1979.96 1205.29,1979.96 1284.68,2059.35 1374.72,2059.35 1407.49,2026.58 1844.87,2026.58 1853.99,2035.7 1907.82,2035.7 1953.99,1989.53 2044.42,1989.53 2081.39,2026.5 2543.21,2026.5 2572.49,1997.22 2653.4,1997.22 2666.32,1984.31 2668.31,1982.32 2688.61,1982.32 2690.59,1984.31 3492.5,1984.31 3506.75,1998.56 3879.89,1998.56 3928.44,1950 4125.94,1950 4174.49,1998.56 4630.42,1998.56 4652.78,1976.2 4652.78,1029.12 4757.81,924.09 v1(4757.81,858.06)
  Bottom Layer w5: U26.9@797.38,2133.57 v1(817.38,2133.57)
FMC_I2C_SDA: R154.1 U26.7 | length 5606.2
  Top Layer w8: v1(4757.81,708.06) 4756.77,709.09 4756.77,803.77 4762.52,809.51 R154.1@4762.52,812.76
  L7 Ctrl Signal 1 w5: v1(817.38,2172.94) 840.78,2172.94 941.54,2072.17 997.39,2072.17 1077.38,1992.19 1194.17,1992.19 1274.15,2072.17 1374.63,2072.17 1411.22,2035.58 1841.15,2035.58 1850.26,2044.7 1911.55,2044.7 1957.71,1998.53 2040.69,1998.53 2080.44,2038.28 2742.33,2038.28 2785.29,1995.32 3490.79,1995.32 3524.69,2029.22 3866.63,2029.22 3936.85,1959 4122.21,1959 4170.77,2007.56 4634.15,2007.56 4661.78,1979.93 4661.78,1034.33 4693.43,1002.67 4741.27,1002.67 4781.02,962.93 4785.2,962.93 4802.69,945.44 4802.69,825.28 4757.81,780.4 v1(4757.81,708.06)
  Bottom Layer w5: U26.7@797.38,2172.94 v1(817.38,2172.94)
FMC_SCLK: PP29.1 R167.1 U29.1 U31.1 | length 4534.3
  Top Layer w5: v1(812.61,1536.41) 812.61,1533.85 v1(841.55,1504.92)
  Top Layer w8: v1(4557.81,858.06) R167.1@4562.52,853.35
  L7 Ctrl Signal 1 w5: v1(841.55,1504.92) 841.55,1505.05 887.78,1551.28 932.97,1551.28 933.6,1551.91 976.76,1551.91 990.79,1537.87 1141.09,1537.87 1155.88,1523.09 1246.93,1523.09 1378.3,1391.72 1387.3,1382.72 1387.3,1159.55 1532.64,1014.21 1663.64,1014.21 1681.55,996.3 1681.55,912.51 1771.01,823.05 1821.56,823.05 1918.8,725.8 PP29.1@1919.48,725.8 1984.25,661.03 2188.84,661.03 2270.87,579 2885.41,579 2911.14,604.73 2988.39,604.73 2991.71,608.06 3418.7,608.06 3442.75,632.1 3567.69,632.1 3660,724.41 4160,724.41 4293.65,858.06 v1(4557.81,858.06)
  Bottom Layer w5: U31.1@787.61,1536.41 v1(812.61,1536.41) ; v1(841.55,1504.92) U29.1@866.55,1504.92
FMC_SCLK_1p8: R137.2 U36.2 | length 248
  Top Layer w5: v1(523.04,1392.03) U36.2@523.04,1423.03
  Bottom Layer w5: v1(523.04,1392.03) 537.52,1392.03 577.47,1431.98 577.47,1506.12 591.99,1520.65 594.41,1520.65 605.84,1532.07 605.84,1532.3 615.49,1541.95 626.09,1541.95 R137.2@631.94,1547.79
FMC_SCLK_3p3: R134.2 U30.2 | length 79.4
  Top Layer w5: U30.2@761.78,1647.44 v1(761.78,1682.44)
  Bottom Layer w5: v1(761.78,1682.44) 761.78,1697.44 772.47,1708.12 774.44,1708.12 781.78,1715.47 R134.2@781.78,1717.44
FMC_SDI: PP27.1 R169.1 U29.2 U31.2 | length 4743.1
  Top Layer w8: R169.1@4603.11,712.76 v1(4607.81,708.06)
  L7 Ctrl Signal 1 w5: v1(764.58,1520.66) 815.75,1520.66 826.05,1510.37 826.05,1498.5 835.13,1489.42 838.44,1489.42 880.33,1447.53 916.36,1447.53 983.07,1514.24 983.07,1517.29 994.66,1528.87 1101.8,1528.87 1116.58,1514.09 1243.2,1514.09 1378.3,1378.99 1378.3,1155.82 1528.91,1005.21 1656.45,1005.21 1672.55,989.11 1672.55,908.78 1767.28,814.05 1803.73,814.05 1863.24,754.54 1863.24,732.05 PP27.1@1919.48,675.8 2025.29,570 2883.07,570 2903.26,549.81 3015.75,549.81 3020.76,554.82 3133.25,554.82 3136.61,551.46 3178.58,551.46 3181.08,553.96 3285.6,553.96 3301.64,570 3561.94,570 3660,668.06 4160,668.06 4249.47,757.53 4583.34,757.53 4607.81,733.06 v1(4607.81,708.06)
  Bottom Layer w5: v1(764.58,1520.66) U31.2@789.58,1520.66 U29.2@864.58,1520.66
FMC_SDI_1p8: U31.11 U36.5 | length 229.8
  Top Layer w5: U36.5@570.28,1423.03 571.28,1424.02 571.28,1449.91 583.66,1462.29 678.71,1462.29 706.59,1490.17 v1(706.59,1520.66)
  Bottom Layer w5: v1(706.59,1520.66) U31.11@726.59,1520.66
FMC_SDI_3p3: U29.11 U30.5 | length 412.8
  Top Layer w5: U30.5@714.53,1647.44 714.74,1647.23 714.74,1619.76 747.06,1587.43 763.07,1587.43 782.22,1606.58 871.61,1606.58 915.75,1606.58 930.69,1591.64 930.69,1531.37 941.4,1520.66 v1(967.57,1520.66)
  Bottom Layer w5: U29.11@927.57,1520.66 v1(967.57,1520.66)
  other v1: 764.51,1588.88
FMC_SDO: PP31.1 R171.1 U31.4 | length 4612.5
  Top Layer w8: R171.1@4603.11,662.76 v1(4607.81,658.06)
  L7 Ctrl Signal 1 w5: v1(809.58,1479.17) 819.22,1469.53 833.71,1469.53 864.71,1438.53 920.08,1438.53 964.23,1482.67 1100.49,1482.67 1122.91,1505.09 1239.47,1505.09 1369.3,1375.26 1369.3,1152.1 1544.13,977.26 1544.13,924.07 1663.15,805.05 1800,805.05 1850,755.05 1850,686.93 1911.13,625.8 PP31.1@1919.48,625.8 1986.29,559 2881.34,559 2899.53,540.81 3103.42,540.81 3120.41,523.82 3587.66,523.82 3660,596.17 4160,596.17 4280.89,717.06 4538.73,717.06 4552.66,730.98 4560.19,730.98 4607.81,683.36 v1(4607.81,658.06)
  Bottom Layer w5: U31.4@789.58,1489.17 791.02,1487.73 800.15,1487.73 808.71,1479.17 v1(809.58,1479.17)
FMC_SDO_DAC_1p8: U35.2 U36.11 | length 105.7
  Top Layer w5: v1(586.03,1612.44) U36.11@586.03,1647.44
  Bottom Layer w5: U35.2@572.25,1547.44 572.25,1598.66 v1(586.03,1612.44)
FMC_SDO_LMK_3p3: U30.11 U32.2 | length 318.5
  Top Layer w5: v1(698.79,1392.03) U30.11@698.79,1423.03
  L7 Ctrl Signal 1 w5: v1(492.25,1514.17) 585.73,1514.17 696.66,1403.24 696.66,1394.15 v1(698.79,1392.03)
  Bottom Layer w5: U32.2@492.25,1489.17 v1(492.25,1514.17)
FPGA_CORECLK_n: C132.1 J10.G7 | length 2617.4
  Top Layer w10: v1(2382.69,2347.02) v1@2383.19,2347.02
  Top Layer w12.3: C132.1@2383.19,2327.02 v1@2383.19,2347.02
  L10 Ctrl Signal 2 w4: v1(2382.69,2347.02) 2382.69,2348.89 2390.16,2356.37 2390.16,2367.48 2407.19,2384.51 2442.85,2384.51 2468.77,2358.59 2768.94,2358.59 2774.22,2353.32 2809.73,2317.81 2815,2312.53 2815,2184.02 2837.36,2161.65 2859.46,2139.55 2906.47,2139.55 2909.1,2136.92 2994.76,2051.26 3459.13,2051.26 3495.39,2015 3885,2015 3928.27,2058.27 4083.73,2058.27 4115.24,2026.75 4127,2015 4600,2015 4615.51,2030.51 4615.51,2045.86 4607.81,2053.56 4585.15,2053.56 4582.81,2051.21 v1(4582.81,2033.06)
FPGA_CORECLK_p: C131.1 J10.G6 | length 2632.3
  Top Layer w10: v1@2406.14,2347.02 v1(2406.64,2347.02)
  Top Layer w12.3: C131.1@2406.14,2327.02 v1@2406.14,2347.02
  L10 Ctrl Signal 2 w4: v1(2406.64,2347.02) 2406.64,2348.89 2399.16,2356.37 2399.16,2363.75 2410.92,2375.51 2439.12,2375.51 2455.17,2359.46 2465.04,2349.59 2765.22,2349.59 2806,2308.81 2806,2180.29 2833.64,2152.65 2850,2136.29 2855.73,2130.55 2902.74,2130.55 2991.03,2042.26 3455.4,2042.26 3491.66,2006 3888.73,2006 3931.99,2049.27 4080,2049.27 4090.76,2038.51 4106.24,2023.03 4123.27,2006 4603.73,2006 4624.51,2026.78 4624.51,2049.59 4611.54,2062.56 4585.15,2062.56 4582.81,2064.9 v1(4582.81,2083.06)
FPGA_SYSREF_n: C140.1 J10.G10 | length 2332.6
  Top Layer w10: v1@2409.66,1711.47 v1(2410.16,1711.47)
  Top Layer w12.5: v1@2409.66,1711.47 C140.1@2409.66,1731.47
  L10 Ctrl Signal 2 w4: v1(2410.16,1711.47) 2405.03,1711.47 2402.69,1713.82 2402.69,1728.44 2417.31,1743.06 2666.17,1743.06 2678.8,1755.68 2685.42,1762.31 3020.07,1762.31 3062.7,1804.94 3154.78,1804.94 3175.65,1784.07 3292.92,1784.07 3313.63,1804.78 3462.97,1804.78 3528.49,1870.3 4316.82,1870.3 4350.07,1903.56 4580.47,1903.56 4582.81,1901.21 v1(4582.81,1883.06)
FPGA_SYSREF_p: C139.1 J10.G9 | length 2347.6
  Top Layer w10: v1(2386.21,1711.47) v1@2386.71,1711.47
  Top Layer w12.5: v1@2386.71,1711.47 C139.1@2386.71,1731.47
  L10 Ctrl Signal 2 w4: v1(2386.21,1711.47) 2391.34,1711.47 2393.69,1713.82 2393.69,1732.17 2413.58,1752.06 2662.44,1752.06 2675.07,1764.68 2681.7,1771.31 3016.34,1771.31 3058.97,1813.94 3158.51,1813.94 3161.15,1811.31 3179.38,1793.07 3289.19,1793.07 3309.9,1813.78 3459.24,1813.78 3524.76,1879.3 4313.09,1879.3 4346.34,1912.56 4580.47,1912.56 4582.81,1914.9 v1(4582.81,1933.06)
GA0_FMC: J10.C34 R173.2 U40.1 | length 741.1
  Top Layer w8: U40.1@4942.49,214.51 4964.49,214.51 4971.68,207.32 4971.68,205.36 4977.52,199.51 v1(4979.49,199.51)
  Bottom Layer w5: v1(4782.81,683.06) 4804.49,661.37 4804.49,634.5 4826.17,612.82 4995.37,612.82 5018.86,589.34 5018.86,346.35 4998.58,326.08 4998.58,218.61 v1(4979.49,199.51)
GA1_FMC: J10.D35 R174.2 U40.2 | length 643.3
  Top Layer w8: U40.2@4942.49,234.2 v1(4979.49,234.2)
  Bottom Layer w5: v1(4732.81,633.06) 4735.94,629.93 4747.97,629.93 4774.07,603.82 4941.81,603.82 4956.75,588.89 4956.75,350.84 4979.49,328.1 v1(4979.49,234.2)
GBTCLK0_FMC_n: C134.1 J10.D5 | length 3049.4
  Top Layer w10: v1(2286.79,2347.02) v1@2287.29,2347.02
  Top Layer w12.3: C134.1@2287.29,2327.02 v1@2287.29,2347.02
  L10 Ctrl Signal 2 w4: v1(2286.79,2347.02) 2286.79,2345.16 2294.27,2337.68 2294.27,2316.48 2313.38,2297.36 2517.72,2297.36 2530.48,2310.12 2752.33,2310.12 2757.72,2304.73 2764.09,2298.36 2773.74,2288.71 2773.74,2023.59 2859.89,1937.43 3296.72,1937.43 3317.17,1916.99 3341.98,1892.18 3516.34,1892.18 3581.1,1956.94 4621.12,1956.94 4657.81,1993.62 4657.81,2143.25 4668.11,2153.56 4730.47,2153.56 4732.81,2151.21 v1(4732.81,2133.06)
GBTCLK0_FMC_p: C133.1 J10.D4 | length 3034.4
  Top Layer w10: v1@2310.24,2347.02 v1(2310.74,2347.02)
  Top Layer w12.3: C133.1@2310.24,2327.02 v1@2310.24,2347.02
  L10 Ctrl Signal 2 w4: v1(2310.74,2347.02) 2310.74,2345.16 2303.27,2337.68 2303.27,2320.21 2317.11,2306.36 2513.99,2306.36 2526.75,2319.12 2756.06,2319.12 2764.09,2311.09 2782.74,2292.44 2782.74,2027.32 2863.62,1946.43 3300.45,1946.43 3323.53,1923.35 3345.7,1901.18 3512.62,1901.18 3577.37,1965.94 4617.4,1965.94 4648.81,1997.35 4648.81,2146.98 4664.39,2162.56 4730.47,2162.56 4732.81,2164.9 v1(4732.81,2183.06)
GBTCLK1_FMC_n: C138.1 J10.B21 | length 3051.5
  Top Layer w10: v1@2326.87,1711.47 v1(2327.37,1711.47)
  Top Layer w12.5: v1@2326.87,1711.47 C138.1@2326.87,1731.47
  L10 Ctrl Signal 2 w4: v1(2327.37,1711.47) 2322.23,1711.47 2319.89,1709.13 2319.89,1683.93 2331.63,1672.19 3011.77,1672.19 3050.74,1711.17 3171.81,1711.17 3188.66,1728.01 3263.08,1728.01 3297.02,1694.07 3586.22,1694.07 3633.14,1740.99 4133.14,1740.99 4159.21,1767.06 4456.85,1767.06 4658.54,1565.36 4817.36,1565.36 4826.36,1556.36 4916.67,1466.06 4916.67,1373.74 4896.48,1353.56 4835.15,1353.56 4832.81,1351.21 v1(4832.81,1333.06)
GBTCLK1_FMC_p: C137.1 J10.B20 | length 3036.6
  Top Layer w10: v1(2303.41,1711.47) v1@2303.91,1711.47
  Top Layer w12.5: v1@2303.91,1711.47 C137.1@2303.91,1731.47
  L10 Ctrl Signal 2 w4: v1(2303.41,1711.47) 2308.55,1711.47 2310.89,1709.13 2310.89,1680.2 2325.27,1665.83 2327.9,1663.19 3015.49,1663.19 3054.47,1702.17 3175.54,1702.17 3192.39,1719.01 3259.35,1719.01 3284.29,1694.07 3293.29,1685.07 3589.95,1685.07 3636.86,1731.99 4136.86,1731.99 4162.93,1758.06 4453.12,1758.06 4654.82,1556.36 4813.64,1556.36 4907.67,1462.33 4907.67,1377.47 4892.75,1362.56 4835.15,1362.56 4832.81,1364.9 v1(4832.81,1383.06)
